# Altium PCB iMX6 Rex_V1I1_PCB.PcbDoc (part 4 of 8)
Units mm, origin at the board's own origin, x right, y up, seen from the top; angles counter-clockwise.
Board outline 70 x 40 mm, 12 copper layers (L1, L2, L3, L4, L5 (PWR), L6 (PWR), L7 (PWR), L8 (PWR), L9, L10, L11, L12), stack 1.566 mm thick; 473 components, 409 nets, 2294 pads, 1880 vias.
Unrouted connection lines stored in the file: 7.
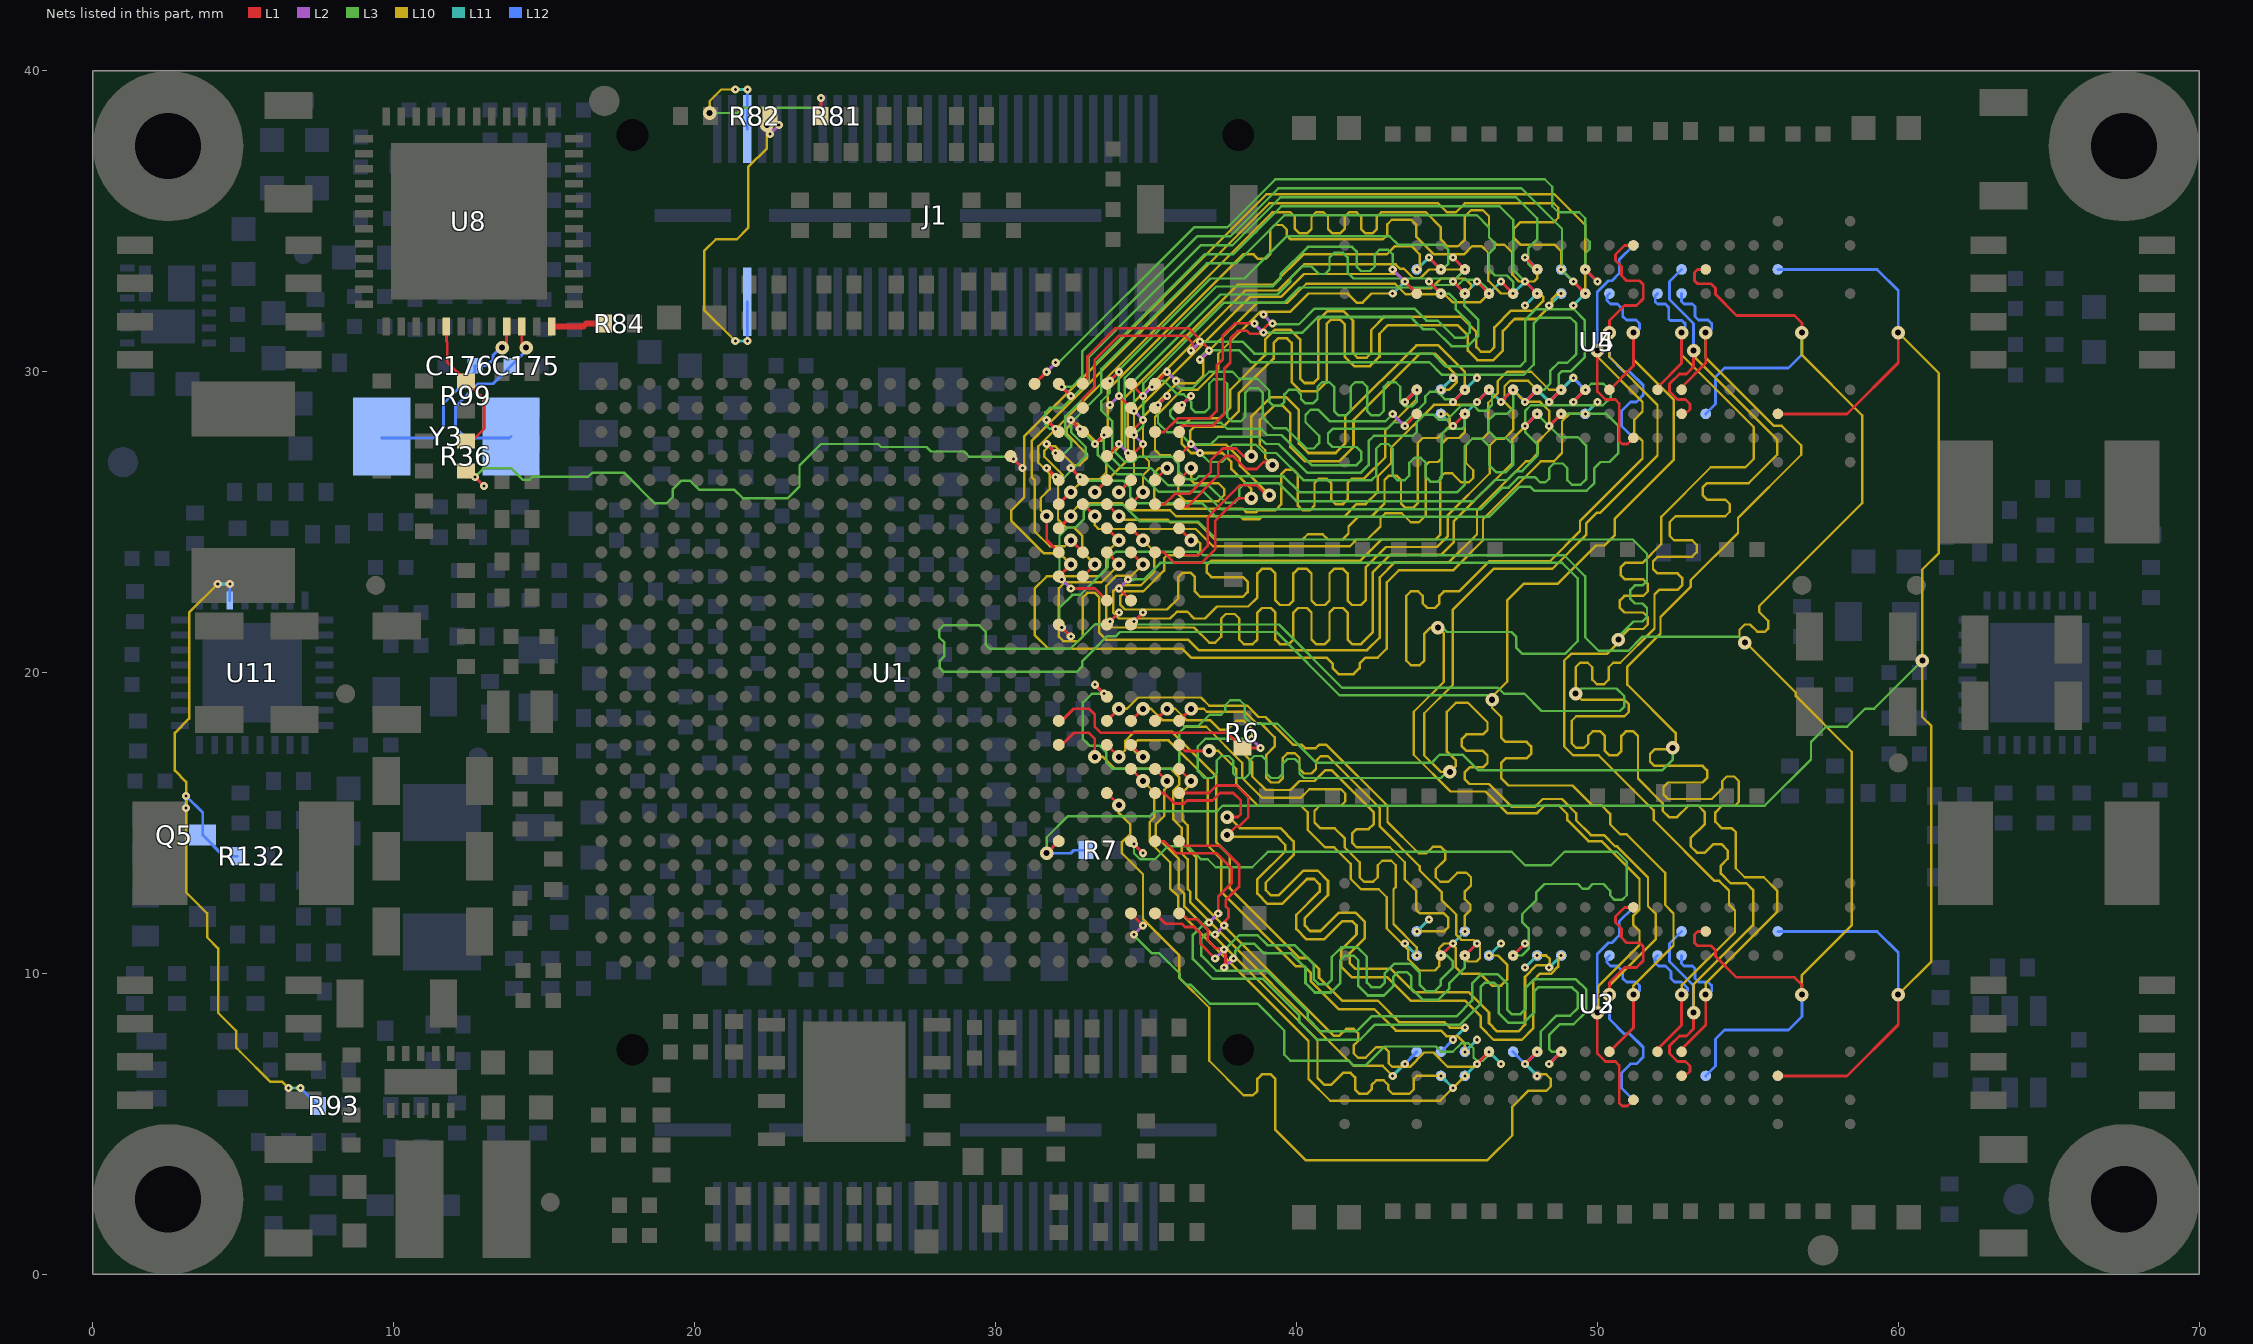
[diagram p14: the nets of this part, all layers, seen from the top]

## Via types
v1: diameter 0.45, hole 0.2, L1 to L12, tented both sides, 761 vias
v2: diameter 0.27, hole 0.1, L1 to L2, 305 vias
v3: diameter 0.27, hole 0.1, L2 to L3, 290 vias
v4: diameter 0.45, hole 0.2, L3 to L10, 196 vias
v5: diameter 0.27, hole 0.1, L11 to L12, 185 vias
v6: diameter 0.27, hole 0.1, L10 to L11, 142 vias
v7: diameter 0.45, hole 0.2, L3 to L10, tented both sides, 1 vias

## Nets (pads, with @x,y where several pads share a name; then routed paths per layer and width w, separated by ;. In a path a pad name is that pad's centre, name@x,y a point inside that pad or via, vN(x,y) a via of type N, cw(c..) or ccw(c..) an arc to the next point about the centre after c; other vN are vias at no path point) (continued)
DRAM_D24: U1.AE9 U3.D7 | length 19.8
  L1 w0.093: U1.AE9@36.1,16.8 v1(36.5,16.4)
  L10 w0.08: v1(36.5,16.4) 36.5,16.3 36.213,16.013 36.213,15.1 36.383,14.93 36.383,14.153 36.675,13.86 36.675,12.495 41.232,7.938 41.43,7.938 41.654,8.162 41.904,8.162 42.054,8.012 42.054,7.762 41.9,7.608 ; 41.9,7.6 41.9,7.35 42.05,7.2 42.3,7.2 42.654,7.554 ; 42.662,7.554 42.912,7.554 43.062,7.404 43.062,7.021 43.183,6.9 43.77,6.9 44.245,7.375 44.555,7.375 45.03,6.9 45.9,6.9 v6(46.4,7.4)
  L11 w0.1: v6(46.4,7.4) v5(46.8,7)
  L12 w0.093: v6(46.4,7.4) v5(46.8,7)
DRAM_D25: U1.Y10 U3.A7 | length 19.9
  L1 w0.093: U1.Y10@32.1,17.6 32.2,17.6 32.6,18 33.1,18 33.3,17.8 v1(33.3,17.2)
  L10 w0.08: v1(33.3,17.2) 33.57,17.2 33.97,16.8 35.83,16.8 36.1,16.53 36.1,16.27 35.909,16.078 35.909,15.122 36.183,14.847 36.183,14 36.383,13.8 36.383,12.813 36.475,12.721 36.475,12.362 41.9,6.937 42.863,6.937 v6(43.2,6.6)
  L11 w0.1: v6(43.2,6.6) v5(43.6,7)
  L12 w0.093: v5(43.6,7) U3.A7@44,7.4
DRAM_D26: U1.AE11 U3.C3 | length 19.8
  L1 w0.093: U1.AE11@36.1,18.4 v1(36.5,18.8)
  L10 w0.08: v1(36.5,18.8) 36.917,18.8 37.017,18.7 38.287,18.7 38.662,18.325 38.805,18.325 39.275,17.855 39.275,17.545 39,17.27 39,16.5 39.15,16.35 39.4,16.35 39.55,16.5 39.55,17.17 39.7,17.32 39.95,17.32 40.1,17.17 40.1,16.8 40.25,16.65 40.5,16.65 40.65,16.8 40.65,17.07 40.8,17.22 41.05,17.22 42.775,15.495 42.775,14.888 44.1,13.563 44.1,13.43 44.825,12.705 44.825,12.445 45.315,11.955 45.315,11.282 45.482,11.115 45.885,11.115 46.1,10.9 46.1,10.52 45.98,10.4 45.7,10.4 45.6,10.5 v6(45.6,10.6)
  L11 w0.1: v6(45.6,10.6) v5(46,11)
  L12 w0.093: v6(45.6,10.6) v5(46,11)
DRAM_D27: U1.AB11 U3.C2 | length 19.8
  L1 w0.093: U1.AB11@33.7,18.4 v1(34.1,18.8)
  L10 w0.08: v1(34.1,18.8) 34.37,18.8 34.745,19.175 36.825,19.175 37.1,18.9 38.37,18.9 38.745,18.525 38.975,18.525 39.9,17.6 40.181,17.6 40.291,17.491 40.641,17.491 40.75,17.6 41,17.6 43.025,15.575 43.025,15.041 44.066,14 44.321,14 44.53,14.209 44.8,14.209 44.95,14.059 44.95,13.789 44.63,13.47 44.63,13.2 44.78,13.05 45.05,13.05 45.35,13.35 45.65,13.35 45.8,13.2 45.8,12.93 45.6,12.73 45.6,12.47 45.785,12.285 45.785,12.115 45.6,11.93 v6(45.6,11.4)
  L11 w0.1: v5(45.2,11) v6(45.6,11.4)
  L12 w0.093: v5(45.2,11) v6(45.6,11.4)
DRAM_D28: U1.AC9 U3.C8 | length 19.8
  L1 w0.093: U1.AC9@34.5,16.8 v1(34.9,16.4)
  L10 w0.08: v1(34.9,16.4) 35.275,16.025 35.275,15.188 35.125,15.038 35.125,14.375 35.8,13.7 35.8,12.83 36.075,12.555 36.075,12.079 40.4,7.754 40.4,6.5 41.125,5.775 44.775,5.775 v6(45.6,6.6)
  L11 w0.1: v6(45.6,6.6) v5(46,7)
  L12 w0.093: v6(45.6,6.6) v5(46,7)
DRAM_D29: U1.AD9 U3.B8 | length 19.8
  L1 w0.093: U1.AD9@35.3,16.8 v1(35.7,16.4)
  L10 w0.08: v1(35.7,16.4) 35.7,16.2 35.604,16.104 35.604,15.235 35.325,14.955 35.325,14.575 36.092,13.809 36.092,12.822 36.275,12.638 36.275,12.225 40.7,7.8 40.7,6.53 40.93,6.3 41.15,6.3 41.55,6.7 41.8,6.7 41.95,6.55 41.95,6.15 42.1,6 42.35,6 42.5,6.15 42.5,6.3 42.65,6.45 42.9,6.45 43.05,6.3 43.05,6.15 43.2,6 43.75,6 43.9,6.15 43.9,6.5 44,6.6 v6(44.8,6.6)
  L11 w0.1: v6(44.8,6.6) v5(45.2,6.2)
  L12 w0.093: v6(44.8,6.6) v5(45.2,6.2)
DRAM_D30: U1.AD11 U3.A2 | length 19.8
  L1 w0.093: U1.AD11@35.3,18.4 v1(35.7,18.8)
  L10 w0.08: v1(35.7,18.8) 35.97,18.8 36.345,18.425 37.132,18.425 37.457,18.1 37.7,18.1 38,18.4 38.243,18.4 38.525,18.118 38.525,17.875 38.225,17.575 38.225,17.332 38.525,17.032 38.525,16.558 38.983,16.1 39.8,16.1 40.1,16.4 40.6,16.4 40.95,16.75 41.18,16.75 42.575,15.355 42.575,14.975 42.4,14.8 42,14.8 41.85,14.65 41.85,14.35 42,14.2 43.1,14.2 43.6,13.7 43.6,13.13 43.975,12.755 43.975,12.125 44.1,12 44.9,12 45.05,11.85 45.05,11.55 44.9,11.4 v6(44,11.4)
  L11 w0.1: v6(44,11.4) v5(44.4,11.8)
  L12 w0.093: v6(44,11.4) v5(44.4,11.8)
DRAM_D31: U1.AC11 U3.A3 | length 19.8
  L1 w0.093: U1.AC11@34.5,18.4 v1(34.9,18.8)
  L10 w0.08: v1(34.9,18.8) 35.17,18.8 35.545,18.425 36.062,18.425 36.287,18.2 37,18.2 38.2,17 38.2,16.5 38.863,15.837 40.137,15.837 40.425,16.125 41.475,16.125 41.625,15.975 41.625,15.725 41.475,15.575 40.775,15.575 40.6,15.4 40.6,15.02 40.795,14.825 41.275,14.825 41.6,14.5 41.6,14.2 42.1,13.7 42.1,13.2 42.25,13.05 42.55,13.05 42.7,13.2 42.7,13.6 42.85,13.75 43.15,13.75 43.3,13.6 43.3,12.875 43.225,12.8 43.225,11.645 44,10.87 v6(44,10.6)
  L11 w0.1: v5(43.6,11) v6(44,10.6)
  L12 w0.093: v5(43.6,11) v6(44,10.6)
DRAM_D32: U1.AA17 U5.E3 | length 31.9
  L1 w0.093: U1.AA17@32.9,23.2 v1(33.3,23.6)
  L10 w0.08: v1(33.3,23.6) 32.875,24.025 32.875,24.555 32.605,24.825 32.345,24.825 32.075,25.095 32.075,26.205 32.235,26.365 32.235,26.565 31.622,27.177 31.622,27.377 31.773,27.527 31.972,27.527 32.6,26.9 32.8,26.9 33.025,27.125 33.025,27.275 32.373,27.928 32.373,28.127 32.523,28.277 32.722,28.277 33.3,27.7 33.5,27.7 33.725,27.925 33.725,29.397 38.228,33.9 38.578,33.9 38.728,33.75 38.978,33.75 39.128,33.9 39.128,34.728 39.278,34.878 39.528,34.878 39.678,34.728 39.678,34.522 39.8,34.4 42.87,34.4 43.02,34.55 43.02,34.9 43.17,35.05 43.815,35.05 43.975,34.89 43.975,34.495 44.57,33.9 45.57,33.9 45.845,34.175 46.155,34.175 46.375,33.955 46.375,33.028 46.803,32.6 v6(47.2,32.6)
  L11 w0.1: v6(47.2,32.6) v5(47.6,33)
  L12 w0.093: v6(47.2,32.6) v5(47.6,33)
DRAM_D33: U1.AA18 U5.G2 | length 31.9
  L1 w0.093: v1(32.5,24.4) U1.AA18@32.9,24
  L10 w0.08: v1(32.5,24.4) 32.3,24.2 31.8,24.2 31.3,24.7 31.3,26.4 31.2,26.5 31.2,27.7 39.1,35.6 44.7,35.6 45,35.3 45.3,35.3 45.6,35.6 48.55,35.6 48.7,35.45 48.7,35.12 48.555,34.975 47.445,34.975 47.225,34.755 47.225,34.445 47.445,34.225 48.575,34.225 48.8,34 v6(48.8,33.4)
  L11 w0.1: v6(48.8,33.4) v5(49.2,33)
  L12 w0.093: v6(48.8,33.4) v5(49.2,33)
DRAM_D34: U1.AC18 U5.F8 | length 31.9
  L1 w0.093: U1.AC18@34.5,24 v1(34.9,23.6)
  L10 w0.08: v1(34.9,23.6) 34.525,23.225 34.021,23.225 33.683,22.887 33.683,21.702 33.885,21.5 36.6,21.5 37.1,21 37.3,21 37.5,21.2 37.5,21.8 37.65,21.95 37.95,21.95 38.1,21.8 38.1,21.1 38.25,20.95 38.55,20.95 38.7,21.1 38.7,22 38.85,22.15 39.15,22.15 39.3,22 39.3,21.1 39.45,20.95 39.75,20.95 39.9,21.1 39.9,22 40.05,22.15 40.35,22.15 40.5,22 40.5,21.1 40.65,20.95 40.95,20.95 41.1,21.1 41.1,22 41.25,22.15 41.55,22.15 41.7,22 41.7,21.1 41.85,20.95 42.15,20.95 42.533,21.333 42.533,23.333 43.125,23.925 44.825,23.925 45.225,24.325 45.225,25.025 47.175,26.975 47.175,27.762 48,28.587 v6(48,28.6)
  L11 w0.1: v5(47.6,28.2) v6(48,28.6)
  L12 w0.093: v5(47.6,28.2) v6(48,28.6)
DRAM_D35: U1.AE19 U5.H7 | length 31.9
  L1 w0.093: U1.AE19@36.1,24.8 v1(36.5,24.4)
  L10 w0.08: v1(36.5,24.4) 36.7,24.4 36.8,24.3 36.8,24 36.7,23.9 35.7,23.9 35.6,23.8 35.6,23.392 34.908,22.7 34.3,22.7 34.15,22.55 34.15,22.25 34.3,22.1 35.7,22.1 36.075,22.475 36.075,23.175 36.225,23.325 36.475,23.325 36.625,23.175 36.625,22.7 36.8,22.525 38.225,22.525 38.375,22.675 38.375,23.025 38.225,23.175 37.175,23.175 37.025,23.325 37.025,23.575 37.175,23.725 42.125,23.725 42.825,24.425 44.625,24.425 44.775,24.575 44.775,26.475 44.925,26.625 45.175,26.625 45.475,26.325 45.725,26.325 45.875,26.475 45.875,26.725 45.625,26.975 45.625,27.555 45.845,27.775 46.18,27.775 46.375,27.97 46.375,28.972 46.685,29.282 46.685,29.685 47,30 47.803,30 48.403,29.4 v6(48.8,29.4)
  L11 w0.1: v6(48.8,29.4) v5(49.2,29.8)
  L12 w0.093: v5(49.2,29.8) U5.H7@49.6,29.4
DRAM_D36: U1.Y17 U5.H3 | length 31.9
  L1 w0.093: U1.Y17@32.1,23.2 v1(32.5,23.6)
  L10 w0.08: v1(32.5,23.6) 32.125,23.975 31.595,23.975 30.525,25.045 30.525,25.4 30.95,25.825 30.95,27.85 39,35.9 48.575,35.9 49.6,34.875 v6(49.6,32.6)
  L11 w0.1: v5(49.2,32.2) v6(49.6,32.6)
  L12 w0.093: v5(49.2,32.2) v6(49.6,32.6)
DRAM_D37: U1.Y18 U5.F2 | length 31.9
  L1 w0.093: v1(31.7,25.2) 31.7,24.4 U1.Y18@32.1,24
  L10 w0.08: v1(31.7,25.2) 31.5,25.4 31.5,25.8 31.8,26.1 31.8,26.6 31.423,26.978 31.423,27.522 39.2,35.3 39.8,35.3 39.95,35.15 39.95,34.75 40.1,34.6 40.35,34.6 40.5,34.75 40.5,35.15 40.65,35.3 40.9,35.3 41.05,35.15 41.05,34.75 41.2,34.6 41.45,34.6 41.6,34.75 41.6,35.15 41.75,35.3 42,35.3 42.15,35.15 42.15,34.75 42.3,34.6 42.525,34.6 42.675,34.75 42.675,35.15 42.825,35.3 44.3,35.3 44.8,34.8 44.8,34.4 45.03,34.17 45.37,34.17 45.6,34.4 45.6,35.17 45.8,35.37 46.2,35.37 46.4,35.17 46.4,34.47 46.645,34.225 46.905,34.225 47.175,33.955 47.175,33.225 47.4,33 47.9,33 48,33.1 v6(48,33.4)
  L11 w0.1: v5(47.6,33.8) v6(48,33.4)
  L12 w0.093: v5(47.6,33.8) v6(48,33.4)
DRAM_D38: U1.AB19 U5.H8 | length 31.9
  L1 w0.093: U1.AB19@33.7,24.8 v1(34.1,24.4)
  L10 w0.08: v1(34.1,24.4) 33.675,23.975 33.675,23.445 33.43,23.2 31.7,23.2 31.3,22.8 31.3,21.25 31.75,20.8 36.2,20.8 36.5,20.5 41,20.5 41.2,20.3 41.2,20.15 41.4,19.95 41.9,19.95 42.1,20.15 42.1,20.3 42.3,20.5 42.7,20.5 43,20.8 43,23 43.4,23.4 45.2,23.4 46.2,24.4 46.2,25.1 48.125,27.025 48.555,27.025 48.825,27.295 48.825,28.355 49.07,28.6 v6(49.6,28.6)
  L11 w0.1: v6(49.6,28.6) v5(50,29)
  L12 w0.093: v6(49.6,28.6) v5(50,29)
DRAM_D39: U1.AC19 U5.F7 | length 31.9
  L1 w0.093: U1.AC19@34.5,24.8 v1(34.9,24.4)
  L10 w0.08: v1(34.9,24.4) 35.275,24.025 35.275,23.35 34.825,22.9 34.1,22.9 33.917,22.717 33.917,21.983 34.1,21.8 35.8,21.8 36.025,22.025 36.375,22.025 36.6,21.8 36.958,21.8 37.358,22.2 38.4,22.2 38.7,22.5 38.7,23.3 38.85,23.45 39.15,23.45 39.3,23.3 39.3,22.4 39.45,22.25 39.75,22.25 39.9,22.4 39.9,23.3 40.05,23.45 40.35,23.45 40.5,23.3 40.5,22.4 40.65,22.25 40.95,22.25 41.1,22.4 41.1,23.3 41.25,23.45 41.55,23.45 41.7,23.3 41.7,22.4 41.85,22.25 42.15,22.25 42.3,22.4 42.3,23.5 42.975,24.175 44.675,24.175 45.025,24.525 45.025,25.225 46.425,26.625 46.425,27.555 46.645,27.775 46.905,27.775 47.2,28.07 47.2,28.715 46.915,29 46.915,29.518 47.097,29.7 47.7,29.7 v6(48,29.4)
  L11 w0.1: v6(48,29.4) v5(48.4,29)
  L12 w0.093: v6(48,29.4) v5(48.4,29)
DRAM_D40: U1.Y19 U5.D7 | length 18.4
  L1 w0.093: U1.Y19@32.1,24.8 v1(32.5,25.2)
  L10 w0.08: v1(32.5,25.2) 32.5,25.3 32.825,25.625 34.205,25.625 34.43,25.4 35.8,25.4 36,25.2 38.125,25.2 38.225,25.1 38.77,25.1 38.845,25.175 41.575,25.175 42,25.6 42.3,25.6 42.7,26 42.7,26.517 43.15,26.967 43.15,27.48 44.57,28.9 45.9,28.9 v6(46.4,29.4)
  L11 w0.1: v6(46.4,29.4) v5(46.8,29)
  L12 w0.093: v6(46.4,29.4) v5(46.8,29)
DRAM_D41: U1.AB20 U5.B8 | length 18.5
  L1 w0.093: U1.AB20@33.7,25.6 v1(34.1,25.2)
  L10 w0.08: v1(34.1,25.2) 34.213,25.088 35.712,25.088 35.8,25 36.713,25 37.288,24.425 40.2,24.425 40.375,24.6 40.87,24.6 41.045,24.425 41.525,24.425 41.73,24.63 41.73,24.861 42.045,25.175 42.475,25.175 42.925,25.625 42.925,26.4 43.075,26.55 43.325,26.55 43.475,26.4 43.475,25.625 43.625,25.475 43.875,25.475 44.025,25.625 44.025,27.625 44.2,27.8 44.7,27.8 45.1,28.2 45.1,28.5 45,28.6 v6(44.8,28.6)
  L11 w0.1: v6(44.8,28.6) v5(45.2,28.2)
  L12 w0.093: v6(44.8,28.6) v5(45.2,28.2)
DRAM_D42: U1.AB21 U5.C2 | length 18.4
  L1 w0.093: v1(33.3,26) U1.AB21@33.7,26.4
  L10 w0.08: v1(33.3,26) 33.313,26 34.4,27.087 34.4,28.8 38.3,32.7 39.383,32.7 40.258,33.575 43.295,33.575 43.445,33.425 43.572,33.425 43.882,33.115 44.118,33.115 44.403,33.4 v6(45.6,33.4)
  L11 w0.1: v5(45.2,33) v6(45.6,33.4)
  L12 w0.093: v5(45.2,33) v6(45.6,33.4)
DRAM_D43: U1.AD21 U5.A7 | length 18.4
  L1 w0.093: U1.AD21@35.3,26.4 v1(35.7,26.8)
  L10 w0.08: v1(35.7,26.8) 35.434,26.8 35.275,26.641 35.275,25.825 35.5,25.6 36,25.6 36.15,25.45 38.22,25.45 38.345,25.325 38.655,25.325 38.73,25.4 39.3,25.4 39.5,25.6 39.5,26.6 39.65,26.75 39.9,26.75 40.05,26.6 40.05,25.55 40.2,25.4 40.45,25.4 40.6,25.55 40.6,26.3 40.75,26.45 41,26.45 41.15,26.3 41.15,25.75 41.3,25.6 41.55,25.6 41.7,25.75 41.7,26.3 41.85,26.45 42.25,26.45 42.95,27.15 42.95,28.05 44,29.1 v6(44,29.4)
  L11 w0.1: v5(43.6,29) v6(44,29.4)
  L12 w0.093: v5(43.6,29) v6(44,29.4)
DRAM_D44: U1.Y20 U5.A2 | length 18.4
  L1 w0.093: U1.Y20@32.1,25.6 v1(32.5,26)
  L10 w0.08: v1(32.5,26) 32.925,26.425 33.455,26.425 33.675,26.645 33.675,27.075 34.2,27.6 34.2,29.046 38.054,32.9 39.23,32.9 40.23,33.9 43,33.9 43.275,34.175 43.825,34.175 44.1,33.9 44.1,33.5 v6(44,33.4)
  L11 w0.1: v6(44,33.4) v5(44.4,33.8)
  L12 w0.093: v6(44,33.4) v5(44.4,33.8)
DRAM_D45: U1.AA20 U5.C8 | length 18.4
  L1 w0.093: U1.AA20@32.9,25.6 v1(33.3,25.2)
  L10 w0.08: v1(33.3,25.2) 33.3,24.9 33.425,24.775 36.655,24.775 37.23,24.2 41.775,24.2 42,24.425 42.355,24.425 42.793,24.863 42.793,25.136 42.957,25.3 43.5,25.3 43.8,25 44.07,25 44.3,25.23 44.3,26.9 44.4,27 44.7,27 44.825,27.125 44.825,27.6 45.025,27.8 45.4,27.8 45.6,28 v6(45.6,28.6)
  L11 w0.1: v6(45.6,28.6) v5(46,29)
  L12 w0.093: v6(45.6,28.6) v5(46,29)
DRAM_D46: U1.AE21 U5.A3 | length 18.5
  L1 w0.093: U1.AE21@36.1,26.4 v1(36.5,26.8)
  L10 w0.08: v1(36.5,26.8) 36.5,26.4 36.6,26.3 37.4,26.3 37.6,26.1 37.6,25.9 37.4,25.7 36.3,25.7 36.075,25.925 36.075,26.955 35.805,27.225 35.475,27.225 35.3,27.4 35.3,28.5 36.2,29.4 36.713,29.4 37.4,30.087 37.4,30.6 38.8,32 39.8,32 40.4,32.6 41.7,32.6 42,32.3 42.2,32.3 42.5,32.6 v6(43.2,32.6)
  L11 w0.1: v6(43.2,32.6) v5(43.6,33)
  L12 w0.093: v5(43.6,33) U5.A3@44,32.6
DRAM_D47: U1.AC21 U5.C3 | length 18.4
  L1 w0.093: v1(34.1,26) U1.AC21@34.5,26.4
  L10 w0.08: v1(34.1,26) 34.6,26.5 34.6,28.63 38.47,32.5 39.5,32.5 40.25,33.25 43.337,33.25 43.812,32.775 44.475,32.775 44.8,33.1 45.6,33.1 45.8,32.9 45.8,32.8 v6(45.6,32.6)
  L11 w0.1: v6(45.6,32.6) v5(46,33)
  L12 w0.093: v6(45.6,32.6) v5(46,33)
DRAM_D48: U1.AC22 U4.D7 | length 17.1
  L1 w0.093: U1.AC22@34.5,27.2 v2(34.9,27.6) ; v2(46,33) v3(46.4,32.6)
  L2 w0.1: v3(34.6,27.9) v2(34.9,27.6) ; v2(46,33) v3(46.4,32.6)
  L3 w0.08: v3(34.6,27.9) 34.915,28.215 34.915,29.618 37.597,32.3 39.6,32.3 40.1,32.8 44.538,32.8 44.623,32.885 45.368,32.885 45.541,33.059 46.041,33.059 46.4,32.7 v3(46.4,32.6)
DRAM_D49: U1.AE22 U4.C2 | length 17.1
  L1 w0.093: U1.AE22@36.1,27.2 v2(36.5,27.6) ; v2(45.2,28.2) v3(45.6,28.6)
  L2 w0.1: v2(36.5,27.6) v3(36.8,27.3) ; v2(45.2,28.2) v3(45.6,28.6)
  L3 w0.08: v3(36.8,27.3) 37.1,27 37.525,27 37.725,27.2 37.725,27.425 37.875,27.575 38.655,27.575 38.93,27.3 39.33,27.3 40.23,26.4 42.5,26.4 42.65,26.55 42.65,27.45 42.8,27.6 43.05,27.6 43.2,27.45 43.2,26.55 43.35,26.4 43.6,26.4 43.75,26.55 43.75,26.97 43.925,27.145 44.125,27.145 44.3,26.97 44.3,26.5 44.45,26.35 44.7,26.35 44.825,26.475 44.825,27.925 45,28.1 45.5,28.1 45.6,28.2 v3(45.6,28.6)
DRAM_D50: U1.AE24 U4.C3 | length 17.1
  L1 w0.093: U1.AE24@36.1,28.8 v2(36.5,29.2) ; v2(45.2,29) v3(45.6,29.4)
  L2 w0.1: v3(36.2,28.9) v2(36.5,29.2) ; v2(45.2,29) v3(45.6,29.4)
  L3 w0.08: v3(36.2,28.9) 36,28.9 35.8,28.7 35.8,28.55 36.05,28.3 37.5,28.3 37.7,28.1 38.825,28.1 39.025,27.9 39.5,27.9 40.5,26.9 42,26.9 42.15,27.05 42.15,27.35 42,27.5 41.2,27.5 41.05,27.65 41.05,27.95 41.2,28.1 43.017,28.1 43.232,28.315 43.615,28.315 44.285,28.985 44.285,29.185 44.435,29.335 44.685,29.335 44.935,29.085 45.285,29.085 v3(45.6,29.4)
DRAM_D51: U1.AC24 U4.B8 | length 17.2
  L1 w0.093: v2(34.1,29.2) U1.AC24@34.5,28.8 ; v2(44.4,33.8) v3(44.8,33.4)
  L2 w0.1: v3(33.8,28.9) v2(34.1,29.2) ; v2(44.4,33.8) v3(44.8,33.4)
  L3 w0.08: v3(33.8,28.9) v2(34.1,29.2) 34.1,30.055 37.145,33.1 38.27,33.1 39.67,34.5 43.1,34.5 43.375,34.225 44.875,34.225 45.05,34.05 45.05,33.6 44.85,33.4 v3(44.8,33.4)
DRAM_D52: U1.AB22 U4.A7 | length 17.2
  L1 w0.093: U1.AB22@33.7,27.2 v2(34.1,27.6) ; v2(43.6,33) U4.A7@44,32.6
  L2 w0.1: v2(34.1,27.6) v3(34.4,27.3) ; v3(43.2,33.4) v2(43.6,33)
  L3 w0.08: v3(34.4,27.3) 34.3,27.4 34.3,29.8 37.333,32.833 39.208,32.833 39.475,33.1 39.475,33.245 40.38,34.15 41.85,34.15 42,34 42,33.5 42.15,33.35 42.45,33.35 42.6,33.5 42.6,33.9 42.75,34.05 43.05,34.05 43.2,33.9 v3(43.2,33.4)
DRAM_D53: U1.AC23 U4.C8 | length 17.2
  L1 w0.093: U1.AC23@34.5,28 v2(34.9,28.4) ; v2(45.2,33.8) v3(45.6,33.4)
  L2 w0.1: v3(34.6,28.7) v2(34.9,28.4) ; v2(45.2,33.8) v3(45.6,33.4)
  L3 w0.08: v3(34.6,28.7) 34.6,29.695 37.471,32.567 39.367,32.567 39.8,33 39.8,33.117 40.183,33.5 40.5,33.5 40.75,33.25 40.95,33.25 41.1,33.4 41.1,33.8 41.25,33.95 41.55,33.95 41.7,33.8 41.7,33.3 41.9,33.1 45.3,33.1 v3(45.6,33.4)
DRAM_D54: U1.AD25 U4.A3 | length 17.1
  L1 w0.093: U1.AD25@35.3,29.6 v2(35.7,30) ; v2(43.6,29) v3(44,29.4)
  L2 w0.1: v2(35.7,30) v3(36,29.7) ; v2(43.6,29) v3(44,29.4)
  L3 w0.08: v3(36,29.7) 36,29.6 36.15,29.45 36.55,29.45 37.1,30 37.87,30 38.1,29.77 38.7,29.77 39.1,29.37 39.1,29 39.225,28.875 39.475,28.875 39.6,29 39.6,29.25 39.75,29.4 40,29.4 40.15,29.25 40.15,29.1 40.3,28.95 40.55,28.95 40.7,29.1 40.7,29.5 40.85,29.65 41.1,29.65 41.25,29.5 41.25,28.7 41.4,28.55 41.65,28.55 41.8,28.7 41.8,29.5 41.95,29.65 42.2,29.65 42.35,29.5 42.35,28.7 42.5,28.55 42.75,28.55 42.9,28.7 42.9,29.5 43.05,29.65 43.3,29.65 43.45,29.5 43.45,29 43.6,28.85 43.85,28.85 44,29 v3(44,29.4)
DRAM_D55: U1.AC25 U4.A2 | length 17.1
  L1 w0.093: U1.AC25@34.5,29.6 v2(34.9,29.2) ; v2(43.6,28.2) U4.A2@44,28.6
  L2 w0.1: v2(34.9,29.2) v3(35.2,29.5) ; v3(43.2,28.6) v2(43.6,28.2)
  L3 w0.08: v3(35.2,29.5) 35.4,29.7 35.597,29.7 36.047,29.25 36.253,29.25 36.5,29.003 36.5,28.8 36.65,28.65 36.95,28.65 37.1,28.8 37.1,29.6 37.25,29.75 37.55,29.75 37.7,29.6 37.7,28.5 37.85,28.35 38.15,28.35 38.3,28.5 38.3,29.3 38.45,29.45 38.737,29.45 38.887,29.3 38.887,28.483 39.245,28.125 39.658,28.125 40.331,27.451 40.575,27.451 40.751,27.628 40.751,27.871 40.3,28.323 40.3,28.566 40.477,28.743 40.72,28.743 41.113,28.35 42.95,28.35 v3(43.2,28.6)
DRAM_D56: U1.AB25 U4.E3 | length 25
  L1 w0.093: U1.AB25@33.7,29.6 v2(34.1,30) ; v2(46.8,29) v3(47.2,29.4)
  L2 w0.1: v3(33.8,29.7) v2(34.1,30) ; v2(46.8,29) v3(47.2,29.4)
  L3 w0.08: v3(33.8,29.7) 33.8,29.303 33.515,29.018 33.515,28.715 33.885,28.345 33.885,27.412 34.282,27.015 34.6,27.015 34.76,27.175 35.855,27.175 36.075,26.955 36.075,26.695 36.345,26.425 36.655,26.425 36.755,26.525 39.575,26.525 40.1,26 45.35,26 45.6,26.25 45.6,27.53 45.845,27.775 46.155,27.775 46.4,27.53 46.4,26.9 46.645,26.655 46.955,26.655 47.2,26.9 47.2,27.575 46.975,27.8 46.62,27.8 46.375,28.045 46.375,28.375 46.6,28.6 47,28.6 47.2,28.8 v3(47.2,29.4)
DRAM_D57: U1.AA21 U4.G2 | length 25
  L1 w0.093: v2(32.5,26.8) U1.AA21@32.9,26.4 ; v2(48.4,28.2) v3(48.8,28.6)
  L2 w0.1: v2(32.5,26.8) v3(32.8,26.5) ; v2(48.4,28.2) v3(48.8,28.6)
  L3 w0.08: v3(32.8,26.5) 32.925,26.375 34.255,26.375 34.475,26.155 34.475,25.85 34.7,25.625 36.875,25.625 37.325,25.175 46.4,25.175 47.4,26.175 47.775,26.175 47.9,26.05 49.65,26.05 49.9,26.3 49.9,26.8 50.1,27 50.4,27 50.7,27.3 50.7,28.2 50.3,28.6 v3(48.8,28.6)
DRAM_D58: U1.Y25 U4.H7 | length 25
  L1 w0.093: U1.Y25@32.1,29.6 v2(32.5,29.2) ; v2(49.2,33) v3(49.6,32.6)
  L2 w0.1: v3(32.2,29.5) v2(32.5,29.2) ; v2(49.2,33) v3(49.6,32.6)
  L3 w0.08: v3(32.2,29.5) 32.53,29.5 32.875,29.845 32.875,30.675 36.7,34.5 37.8,34.5 39.4,36.1 47.48,36.1 48.825,34.755 48.825,33.375 v3(49.6,32.6)
DRAM_D59: U1.Y22 U4.F7 | length 25
  L1 w0.093: v2(31.7,27.6) U1.Y22@32.1,27.2 ; v2(47.6,33) v3(48,32.6)
  L2 w0.1: v2(31.7,27.6) v3(32,27.3) ; v2(47.6,33) v3(48,32.6)
  L3 w0.08: v3(32,27.3) 32.3,27.3 32.514,27.514 32.514,27.7 32.315,27.899 32.315,28.515 33.3,29.5 33.3,30.255 36.945,33.9 37.9,33.9 39.5,35.5 46.75,35.5 47.2,35.05 47.2,33.4 v3(48,32.6)
DRAM_D60: U1.AB23 U4.H3 | length 25
  L1 w0.093: v2(33.3,27.6) U1.AB23@33.7,28 ; v2(49.2,29) v3(49.6,29.4)
  L2 w0.1: v2(33.3,27.6) v3(33.6,27.9) ; v2(49.2,29) v3(49.6,29.4)
  L3 w0.08: v3(33.6,27.9) 33.6,27.4 34.198,26.802 35.164,26.802 35.741,26.225 37.075,26.225 37.65,25.65 37.95,25.65 38.1,25.8 38.1,26.1 38.3,26.3 39.4,26.3 40,25.7 45.89,25.7 46.594,26.404 47,26.404 47.296,26.7 47.5,26.7 48,27.2 48,27.6 47.6,28 47.6,28.7 47.785,28.885 50.185,28.885 50.45,29.15 50.45,29.35 50.2,29.6 49.8,29.6 v3(49.6,29.4)
DRAM_D61: U1.AA23 U4.F2 | length 25
  L1 w0.093: v2(32.5,28.4) U1.AA23@32.9,28 ; v2(47.6,28.2) v3(48,28.6)
  L2 w0.1: v2(32.5,28.4) v3(32.8,28.1) ; v2(47.6,28.2) v3(48,28.6)
  L3 w0.08: v3(32.8,28.1) 33.4,27.5 33.4,27.23 34.042,26.588 34.842,26.588 35.418,26.012 36.913,26.012 37.5,25.425 46.125,25.425 46.852,26.152 47.052,26.152 47.4,26.5 47.926,26.5 48.1,26.326 48.276,26.326 48.4,26.45 48.4,26.8 48.55,26.95 48.85,26.95 49,26.8 49,26.4 49.15,26.25 49.45,26.25 49.625,26.425 49.625,27.555 49.355,27.825 48.775,27.825 v3(48,28.6)
DRAM_D62: U1.Y23 U4.F8 | length 25
  L1 w0.093: v2(31.7,28.4) U1.Y23@32.1,28 ; v2(47.6,33.8) v3(48,33.4)
  L2 w0.1: v2(31.7,28.4) v3(32,28.1) ; v2(47.6,33.8) v3(48,33.4)
  L3 w0.08: v3(32,28.1) 31.8,28.1 31.65,28.25 31.65,28.65 31.8,28.8 32.2,28.8 33.1,29.7 33.1,30.489 36.811,34.2 37.866,34.2 39.466,35.8 47.3,35.8 48,35.1 48,34.4 47.7,34.1 47.7,33.6 47.9,33.4 v3(48,33.4)
DRAM_D63: U1.W25 U4.H8 | length 25
  L1 w0.093: U1.W25@31.3,29.6 v2(31.7,30) ; v3(49.6,33.4) v2(50,33)
  L2 w0.1: v2(31.7,30) v3(32,30.3) ; v3(49.6,33.4) v2(50,33)
  L3 w0.08: v3(32,30.3) 32.095,30.3 36.595,34.8 37.7,34.8 39.3,36.4 48.25,36.4 48.5,36.15 48.5,35.5 48.7,35.3 49.4,35.3 49.6,35.1 49.6,34.47 49.75,34.32 49.75,34.08 49.6,33.93 v3(49.6,33.4)
DRAM_DQM0: U1.AC3 U2.D3 | length 17.3
  L1 w0.093: U1.AC3@34.5,12 v2(34.9,11.6) ; v2(46,7) v3(46.4,7.4)
  L2 w0.1: v3(34.6,11.3) v2(34.9,11.6) ; v2(46,7) v3(46.4,7.4)
  L3 w0.08: v3(34.6,11.3) 34.6,11.269 35.2,10.669 35.448,10.669 36.125,9.992 36.125,9.845 36.345,9.625 36.492,9.625 37.117,9 38.7,9 39.6,8.1 39.6,7.3 39.8,7.1 41.75,7.1 41.9,6.95 42.3,6.95 42.925,7.575 44.638,7.575 44.813,7.4 45.197,7.4 45.482,7.685 45.718,7.685 45.885,7.518 45.885,7.215 46,7.1 46.2,7.1 46.4,7.3 v3(46.4,7.4)
DRAM_DQM1: U1.AC6 U2.E7 | length 27.6
  L1 w0.093: U1.AC6@34.5,14.4 v2(34.9,14) ; v3(47.2,10.6) v2(47.6,11)
  L2 w0.1: v3(34.6,14.3) v2(34.9,14) ; v3(47.2,10.6) v2(47.6,11)
  L3 w0.08: v3(34.6,14.3) 34.6,14 34.8,13.8 35.3,13.8 35.725,14.225 36.4,14.225 36.825,13.8 37.051,13.8 37.32,13.531 38.531,13.531 39.05,14.05 47.15,14.05 47.6,13.6 48.46,13.6 48.91,14.05 50.65,14.05 50.975,13.725 50.975,12.6 50.825,12.45 50.575,12.45 50.425,12.6 50.425,12.75 50.2,12.975 49.845,12.975 49.685,12.815 49.515,12.815 49.355,12.975 48.245,12.975 47.975,12.705 47.975,12.445 47.5,11.97 47.5,11.715 47.715,11.5 47.715,10.815 47.5,10.6 v3(47.2,10.6)
DRAM_DQM2: U1.AB8 U3.E7 | length 28.5
  L1 w0.093: U1.AB8@33.7,16 v1(34.1,15.6)
  L10 w0.08: v1(34.1,15.6) 34.1,15.33 34.475,14.955 34.475,14.645 34.2,14.37 34.2,14 34.9,13.3 34.9,11.817 36.1,10.617 36.1,9.866 37.1,8.866 37.1,7.1 38.25,5.95 38.55,5.95 38.7,6.1 38.7,6.5 38.85,6.65 39.15,6.65 39.3,6.5 39.3,4.8 40.3,3.8 46.35,3.8 47.175,4.625 47.175,5.575 47.7,6.1 48.3,6.1 48.45,6.25 48.45,6.5 48.3,6.65 48.05,6.65 v6(48,6.6)
  L11 w0.1: v5(47.6,7) v6(48,6.6)
  L12 w0.093: U3.E7@47.2,7.4 v5(47.6,7)
DRAM_DQM3: U1.AE10 U3.D3 | length 19.8
  L1 w0.093: U1.AE10@36.1,17.6 36.3,17.4 v1(37.1,17.4)
  L10 w0.08: v1(37.1,17.4) 37.4,17.4 38,16.8 38,16.3 38.725,15.575 40.155,15.575 40.375,15.355 40.375,14.775 40.95,14.2 41.25,14.2 41.8,13.65 41.8,13.15 42.15,12.8 42.737,12.8 43,12.537 43,11.5 43.715,10.785 43.715,10.482 44.097,10.1 44.6,10.1 44.748,10.248 44.748,10.848 44.9,11 45.148,11 45.3,10.848 45.3,10.2 45.5,10 46.1,10 46.5,9.6 46.8,9.6 47,9.8 47,10.3 46.7,10.6 v6(46.4,10.6)
  L11 w0.1: v6(46.4,10.6) v5(46.8,11)
  L12 w0.093: v6(46.4,10.6) v5(46.8,11)
DRAM_DQM4: U1.AB18 U5.E7 | length 31.9
  L1 w0.093: U1.AB18@33.7,24 v1(34.1,23.6)
  L10 w0.08: v1(34.1,23.6) 34.1,23.587 33.513,23 32.3,23 32.1,22.8 32.1,21.2 32.25,21.05 32.747,21.05 32.9,21.203 32.9,22.5 33.05,22.65 33.3,22.65 33.45,22.5 33.45,21.317 33.667,21.1 36.4,21.1 36.75,20.75 42.35,20.75 42.767,21.167 42.767,23.167 43.275,23.675 45.075,23.675 46,24.6 46,25.4 47.625,27.025 47.755,27.025 48.025,27.295 48.025,27.683 48.4,28.058 48.4,28.7 48.1,29 v5(47.6,29) v6(47.2,29.4)
  L11 w0.1: v6(47.2,29.4) v5(47.6,29)
  L12 w0.093: v6(47.2,29.4) v5(47.6,29)
DRAM_DQM5: U1.AC20 U5.D3 | length 18.4
  L1 w0.093: U1.AC20@34.5,25.6 v1(34.9,26)
  L10 w0.08: v1(34.9,26) 34.9,26.563 35.1,26.763 35.1,27.025 34.9,27.225 34.9,28.5 36.025,29.625 36.655,29.625 36.9,29.87 36.9,30.5 38.7,32.3 39.7,32.3 40.325,32.925 43.278,32.925 43.628,32.575 44.925,32.575 45.185,32.315 46.115,32.315 v6(46.4,32.6)
  L11 w0.1: v6(46.4,32.6) v5(46.8,33)
  L12 w0.093: v6(46.4,32.6) v5(46.8,33)
DRAM_DQM6: U1.AD24 U4.D3 | length 17.1
  L1 w0.093: U1.AD24@35.3,28.8 v2(35.7,29.2) ; v2(46,29) v3(46.4,29.4)
  L2 w0.1: v3(35.4,28.9) v2(35.7,29.2) ; v2(46,29) v3(46.4,29.4)
  L3 w0.08: v3(35.4,28.9) 35.4,28.3 35.71,27.99 36.095,27.99 36.5,27.585 37.147,27.585 37.4,27.837 38.747,27.837 38.984,27.6 39.4,27.6 40.35,26.65 42.15,26.65 42.4,26.9 42.4,27.7 42.573,27.873 43.873,27.873 44,28 44,28.33 44.245,28.575 44.555,28.575 44.73,28.4 44.997,28.4 45.482,28.885 45.885,28.885 46.07,28.7 46.3,28.7 46.5,28.9 46.5,29.3 v3(46.4,29.4)
DRAM_DQM7: U1.Y21 U4.E7 | length 25
  L1 w0.093: v2(31.7,26.8) U1.Y21@32.1,26.4 ; v2(46.8,33) v3(47.2,32.6)
  L2 w0.1: v2(31.7,26.8) v3(32,26.5) ; v2(46.8,33) v3(47.2,32.6)
  L3 w0.08: v3(32,26.5) 32.3,26.5 33,27.2 33,27.497 32.515,27.982 32.515,28.315 33.515,29.315 33.515,30.095 37.02,33.6 38,33.6 39.6,35.2 46,35.2 46.4,34.8 46.4,34.47 46.585,34.285 46.585,34.115 46.4,33.93 46.4,33.4 46.6,33.2 47,33.2 47.2,33 v3(47.2,32.6)
DRAM_DQS0_N: U1.AD3 U2.B7 | length 17.4
  L1 w0.09: U1.AD3@35.3,12 35.645,11.655 36.191,11.655 36.296,11.55 36.6,11.55 36.804,11.346 36.804,10.996 v2(37.3,10.5) ; v3(44.8,10.6) v2(45.2,11)
  L2 w0.1: v2(37.3,10.5) v3(37.6,10.8) ; v3(44.8,10.6) v2(45.2,11)
  L3 w0.085: v3(37.6,10.8) 37.624,10.8 38.097,11.273 38.708,11.273 39.033,10.948 39.94,10.948 40.58,10.308 40.58,9.8 40.73,9.65 41.03,9.65 41.18,9.8 41.18,10.542 ; 41.18,10.558 41.494,10.872 42.026,10.872 42.34,10.558 42.34,9.7 42.49,9.55 42.79,9.55 42.94,9.7 42.94,10.016 43.254,10.33 43.786,10.33 44.1,10.016 44.1,9.616 44.3,9.416 44.6,9.416 44.8,9.616 44.8,9.796 45.2,10.196 45.2,10.4 45,10.6 v3(44.8,10.6)
DRAM_DQS0_P: U1.AE3 U2.C7 | length 17.4
  L1 w0.09: U1.AE3@36.1,12 36.2,12 36.4,11.8 36.704,11.8 37.054,11.45 37.054,11.1 37.314,10.84 37.441,10.84 37.64,10.641 37.64,10.24 v2(37.6,10.2) ; v3(45.6,10.6) v2(46,11)
  L2 w0.1: v2(37.6,10.2) v3(37.9,10.5) ; v3(45.6,10.6) v2(46,11)
  L3 w0.085: v3(37.9,10.5) 37.973,10.573 37.973,10.753 38.213,10.993 38.592,10.993 38.917,10.668 39.825,10.668 40.3,10.192 40.3,9.684 40.614,9.37 41.146,9.37 41.46,9.684 41.46,10.442 41.61,10.592 41.91,10.592 42.06,10.442 42.06,9.584 42.374,9.27 42.906,9.27 43.22,9.584 43.22,9.9 43.37,10.05 43.67,10.05 43.82,9.9 43.82,9.5 44.184,9.136 44.716,9.136 45.08,9.5 45.08,9.68 45.6,10.2 v3(45.6,10.6)
DRAM_DQS1_N: U1.AE6 U2.G3 | length 27.6
  L1 w0.09: U1.AE6@36.1,14.4 36.25,14.25 37.45,14.25 38.1,13.6 38.1,12.9 37.65,12.45 37.65,12.231 37.74,12.141 37.74,11.859 37.6,11.719 v2(37.6,11.6) ; v2(48.4,7) v3(48.8,7.4)
  L2 w0.1: v3(37.3,11.3) v2(37.6,11.6) ; v2(48.4,7) v3(48.8,7.4)
  L3 w0.085: v3(37.3,11.3) 36.973,11.3 36.84,11.168 36.84,10.594 37.334,10.1 39,10.1 40.38,8.72 40.38,8.5 40.8,8.08 42,8.08 42.5,8.58 45.32,8.58 45.84,9.1 45.84,9.666 46.154,9.98 46.686,9.98 47,9.666 47,8.8 47.15,8.65 47.45,8.65 47.62,8.82 47.62,9.52 47.918,9.818 49.278,9.818 49.632,9.463 49.632,8.737 49.216,8.32 48.766,8.32 48.4,7.954 48.4,7.5 48.5,7.4 v3(48.8,7.4)
DRAM_DQS1_P: U1.AD6 U2.F3 | length 27.6
  L1 w0.09: U1.AD6@35.3,14.4 35.6,14.4 36,14 37.346,14 37.85,13.496 37.85,13.004 37.4,12.554 v2(37.4,12) ; v2(47.6,7) v3(48,7.4)
  L2 w0.1: v3(37.1,11.7) v2(37.4,12) ; v2(47.6,7) v3(48,7.4)
  L3 w0.085: v3(37.1,11.7) 36.977,11.7 36.56,11.283 36.56,10.478 37.218,9.82 38.884,9.82 40.1,8.604 40.1,8.384 40.684,7.8 42.116,7.8 42.616,8.3 45.436,8.3 46.12,8.984 46.12,9.55 46.27,9.7 46.57,9.7 46.72,9.55 46.72,8.704 ; 46.72,8.684 47.034,8.37 47.566,8.37 47.9,8.704 47.9,9.404 48.034,9.538 49.162,9.538 49.352,9.348 49.352,8.852 49.1,8.6 48.65,8.6 48.12,8.07 48.12,7.52 v3(48,7.4)
DRAM_DQS2_N: U1.AE8 U3.G3 | length 28.6
  L1 w0.09: U1.AE8@36.1,16 37.1,16 37.35,16.25 38.004,16.25 38.4,15.854 38.4,15.196 38.104,14.9 38.008,14.9 37.708,14.6 v1(37.7,14.6)
  L10 w0.085: v1(37.7,14.6) 37.748,14.552 39.352,14.552 39.628,14.276 39.628,14.064 38.7,13.135 38.7,12.656 39.041,12.315 39.52,12.315 40.348,13.143 40.592,13.143 40.768,12.967 40.768,12.723 40,11.955 40,11.476 40.341,11.135 40.916,11.135 41.516,11.735 41.861,11.735 41.996,11.6 41.996,11.3 41.496,10.8 41.496,10.225 41.837,9.884 43.012,9.884 43.796,9.1 45.604,9.1 46.12,8.584 46.12,8.234 46.554,7.8 47.492,7.8 47.876,8.184 47.876,9.776 48.1,10 48.471,10 48.7,10.229 48.7,10.5 v6(48.8,10.6)
  L11 w0.1: v5(48.4,10.2) v6(48.8,10.6)
  L12 w0.09: v5(48.4,10.2) v6(48.8,10.6)
DRAM_DQS2_P: U1.AD8 U3.F3 | length 28.6
  L1 w0.09: U1.AD8@35.3,16 35.605,16 35.955,15.65 36.27,15.65 36.37,15.75 37.204,15.75 37.454,16 37.9,16 38.15,15.75 38.15,15.3 38.05,15.2 37.75,15.2 v1(37.7,15.2)
  L10 w0.085: v1(37.7,15.2) 37.754,15.2 38.122,14.833 39.468,14.833 39.908,14.392 39.908,13.948 38.98,13.019 38.98,12.772 39.157,12.595 39.404,12.595 40.233,13.423 40.708,13.423 41.048,13.083 41.048,12.607 40.28,11.839 40.28,11.592 40.457,11.415 40.8,11.415 41.4,12.015 41.977,12.015 42.276,11.716 42.276,11.184 41.776,10.684 41.776,10.341 41.953,10.164 43.128,10.164 43.912,9.38 45.72,9.38 46.4,8.7 46.4,8.35 46.67,8.08 47.376,8.08 47.596,8.3 47.596,9.892 47.984,10.28 48.355,10.28 48.42,10.345 48.42,10.48 48.3,10.6 v6(48,10.6)
  L11 w0.1: v5(47.6,10.2) v6(48,10.6)
  L12 w0.09: v5(47.6,10.2) v6(48,10.6)
DRAM_DQS3_N: U1.AB10 U3.B7 | length 19.9
  L1 w0.09: U1.AB10@33.7,17.6 v1(34.1,17.2)
  L10 w0.085: v1(34.1,17.2) 34.1,17.22 34.31,17.43 34.31,17.736 34.604,18.03 35.87,18.03 37.332,16.568 37.332,14.368 37.78,13.92 37.78,12.836 40.1,10.516 40.384,10.516 40.75,10.15 40.75,9.866 41.518,9.098 42.702,9.098 43.42,8.38 44.92,8.38 45.1,8.2 v6(45.6,8.2)
  L11 w0.1: v5(45.2,7.8) v6(45.6,8.2)
  L12 w0.09: U3.B7@44.8,7.4 v5(45.2,7.8)
DRAM_DQS3_P: U1.AC10 U3.C7 | length 19.9
  L1 w0.09: U1.AC10@34.5,17.6 v1(34.9,17.2)
  L10 w0.085: v1(34.9,17.2) 34.814,17.2 34.59,17.424 34.59,17.62 34.72,17.75 35.754,17.75 37.052,16.452 37.052,14.252 37.5,13.804 37.5,12.72 39.984,10.236 40.268,10.236 40.47,10.034 40.47,9.75 41.402,8.818 42.586,8.818 43.304,8.1 44.804,8.1 44.984,7.92 45.35,7.92 45.6,7.67 v6(45.6,7.4)
  L11 w0.1: v6(45.6,7.4) v5(46,7.8)
  L12 w0.09: v6(45.6,7.4) v5(46,7.8)
DRAM_DQS4_N: U1.AE18 U5.G3 | length 32
  L1 w0.09: U1.AE18@36.1,24 36.2,23.9 36.746,23.9 37.05,24.204 37.05,25.15 38.13,26.23 38.678,26.23 39.008,25.9 v1(39.1,25.9)
  L10 w0.085: v1(39.1,25.9) 38.117,26.883 38.117,27.115 37.652,27.58 36.616,27.58 36.466,27.73 36.466,28.03 36.616,28.18 37.576,28.18 38.08,28.684 38.08,29.28 39.24,30.44 39.24,30.96 39.39,31.11 39.69,31.11 39.84,30.96 39.84,29.66 40.154,29.346 40.686,29.346 41,29.66 41,31.584 41.15,31.734 41.45,31.734 41.6,31.584 41.6,30.5 41.914,30.186 42.446,30.186 42.76,30.5 42.76,31.264 43.048,31.552 45.348,31.552 45.7,31.2 45.7,30.7 46.014,30.386 46.546,30.386 46.86,30.7 46.86,31.36 47.254,31.754 48,31.754 48.48,32.234 48.48,32.4 48.68,32.6 v6(48.8,32.6)
  L11 w0.1: v5(48.4,32.2) v6(48.8,32.6)
  L12 w0.09: v5(48.4,32.2) v6(48.8,32.6)
DRAM_DQS4_P: U1.AD18 U5.F3 | length 32
  L1 w0.09: U1.AD18@35.3,24 35.6,24 35.95,23.65 36.85,23.65 37.3,24.1 37.3,25.046 38.054,25.8 v1(38.5,25.8)
  L10 w0.085: v1(38.5,25.8) 38.5,26.104 37.837,26.767 37.837,26.999 37.536,27.3 36.5,27.3 36.186,27.614 36.186,28.146 36.5,28.46 37.46,28.46 37.8,28.8 37.8,29.396 38.96,30.556 38.96,31.076 39.274,31.39 39.806,31.39 40.12,31.076 40.12,29.776 40.27,29.626 40.57,29.626 40.72,29.776 40.72,31.7 41.034,32.014 41.566,32.014 41.88,31.7 41.88,30.616 42.03,30.466 42.33,30.466 42.48,30.616 42.48,31.38 42.932,31.832 45.463,31.832 45.98,31.316 45.98,30.816 46.13,30.666 46.43,30.666 46.58,30.816 46.58,31.476 47.138,32.034 47.884,32.034 48.2,32.35 48.2,32.5 48.1,32.6 v6(48,32.6)
  L11 w0.1: v5(47.6,32.2) v6(48,32.6)
  L12 w0.09: v5(47.6,32.2) v6(48,32.6)
DRAM_DQS5_N: U1.AE20 U5.B7 | length 18.5
  L1 w0.09: U1.AE20@36.1,25.6 36.19,25.51 36.356,25.51 37.4,26.554 37.4,26.946 37.654,27.2 37.892,27.2 38.322,26.77 38.678,26.77 38.908,27 39.1,27 v1(39.2,26.9)
  L10 w0.085: v1(39.2,26.9) 38.963,27.137 38.963,27.392 38.78,27.574 38.78,28.4 39.248,28.868 39.552,28.868 39.8,28.62 39.8,27.5 40.28,27.02 41.416,27.02 41.896,27.5 41.896,28.396 44.1,30.6 44.6,30.6 45.32,29.88 45.32,29.647 45.073,29.4 v6(44.8,29.4)
  L11 w0.1: v6(44.8,29.4) v5(45.2,29.8)
  L12 w0.09: v6(44.8,29.4) v5(45.2,29.8)
DRAM_DQS5_P: U1.AD20 U5.C7 | length 18.5
  L1 w0.09: U1.AD20@35.3,25.6 35.612,25.6 35.957,25.945 36.438,25.945 37.15,26.657 37.15,27.05 37.55,27.45 37.995,27.45 38.245,27.2 v1(38.5,27.2)
  L10 w0.085: v1(38.5,27.2) 38.5,28.516 39.132,29.148 39.668,29.148 40.08,28.736 40.08,27.616 40.396,27.3 41.3,27.3 41.616,27.616 41.616,28.512 43.984,30.88 44.716,30.88 45.6,29.996 v6(45.6,29.4)
  L11 w0.1: v6(45.6,29.4) v5(46,29.8)
  L12 w0.09: v6(45.6,29.4) v5(46,29.8)
DRAM_DQS6_N: U1.AE23 U4.B7 | length 17.2
  L1 w0.09: U1.AE23@36.1,28 36.1,28.141 36.164,28.205 37.212,28.205 37.6,28.593 37.6,30.1 37.8,30.3 37.8,31.1 38.06,31.36 38.36,31.36 38.459,31.26 38.741,31.26 39.081,31.6 v2(39.2,31.6) ; v2(44.4,33) v3(44.8,32.6)
  L2 w0.1: v3(38.9,31.9) v2(39.2,31.6) ; v2(44.4,33) v3(44.8,32.6)
  L3 w0.085: v3(38.9,31.9) 39.22,31.58 40.08,31.58 40.6,32.1 43.916,32.1 44.316,31.7 44.696,31.7 45.266,31.13 45.585,31.13 45.755,31.3 45.755,31.619 45.3,32.074 45.3,32.373 45.073,32.6 v3(44.8,32.6)
DRAM_DQS6_P: U1.AD23 U4.C7 | length 17.2
  L1 w0.09: U1.AD23@35.3,28 35.605,28 36.06,28.455 37.109,28.455 37.35,28.696 37.35,30.204 37.55,30.404 37.55,31.204 37.956,31.61 38.59,31.61 v2(38.6,31.6) ; v2(45.2,33) v3(45.6,32.6)
  L2 w0.1: v2(38.6,31.6) v3(38.9,31.3) ; v2(45.2,33) v3(45.6,32.6)
  L3 w0.085: v3(38.9,31.3) 40.196,31.3 40.716,31.82 43.8,31.82 43.91,31.71 44.2,31.42 44.58,31.42 45.15,30.85 45.701,30.85 46.035,31.184 46.035,31.735 45.58,32.19 45.58,32.58 v3(45.6,32.6)
DRAM_DQS7_N: U1.AA24 U4.G3 | length 25
  L1 w0.09: U1.AA24@32.9,28.8 32.9,29.112 33.3,29.512 33.3,30.401 34.099,31.2 36.303,31.2 36.552,30.952 36.552,30.752 v2(36.5,30.7) ; v2(48.4,29) v3(48.8,29.4)
  L2 w0.1: v2(36.5,30.7) v3(36.8,31) ; v2(48.4,29) v3(48.8,29.4)
  L3 w0.085: v3(36.8,31) 38.2,31 38.6,30.6 44.53,30.6 44.95,30.18 47.43,30.18 47.6,30.35 47.6,31.716 47.964,32.08 49.216,32.08 49.58,31.716 49.58,30.48 49.12,30.02 48.82,30.02 48.72,29.92 48.72,29.48 v3(48.8,29.4)
DRAM_DQS7_P: U1.AA25 U4.F3 | length 25
  L1 w0.09: U1.AA25@32.9,29.6 33.05,29.75 33.05,30.505 33.995,31.45 36.407,31.45 37.1,30.757 v2(37.1,30.7) ; v2(47.6,29) v3(48,29.4)
  L2 w0.1: v3(36.8,30.4) v2(37.1,30.7) ; v2(47.6,29) v3(48,29.4)
  L3 w0.085: v3(36.8,30.4) 36.8,30.469 37.051,30.72 38.084,30.72 38.484,30.32 44.414,30.32 44.824,29.91 ; 44.834,29.9 47.546,29.9 47.88,30.234 47.88,31.6 48.08,31.8 49.1,31.8 49.3,31.6 49.3,30.596 49.004,30.3 48.704,30.3 48.44,30.036 48.44,29.618 48.222,29.4 v3(48,29.4)
DRAM_RAS_B: U1.AB15 U2.J3 U3.J3 U4.J3 U5.J3 | length 70.1
  L1 w0.093: U1.AB15@33.7,21.6 v2(34.1,22) ; U2.J3@50.4,7.4 51.2,8.2 v1(51.2,9.3) ; U4.J3@50.4,29.4 51.2,30.2 v1(51.2,31.3)
  L2 w0.1: v3(33.8,21.7) v2(34.1,22)
  L3 w0.08: v3(33.8,21.7) 33.715,21.615 33.312,21.615 32.497,20.8 29.8,20.8 29.675,20.925 29.675,21.355 29.455,21.575 28.275,21.575 28.125,21.425 28.125,21.175 28.3,21 28.3,20.55 28.15,20.4 28.15,20.15 28.275,20.025 32.7,20.025 32.875,20.2 32.875,20.372 33.285,20.782 33.285,20.788 33.712,21.215 34.001,21.215 34.136,21.35 39.335,21.35 41.435,19.25 46.35,19.25 v4(46.5,19.1)
  L10 w0.08: v1(51.2,9.3) 51.2,9.6 52.533,10.933 52.533,12 52.255,12.278 52.255,13.345 50.975,14.625 50.762,14.625 50.425,14.962 50.425,15.305 50.13,15.6 49.825,15.6 49.175,16.25 47.05,16.25 46.8,16.5 46.8,17 46.95,17.15 47.65,17.15 47.8,17.3 47.8,17.55 47.65,17.7 46.95,17.7 46.8,17.85 46.8,18.533 46.5,18.833 v4(46.5,19.1) 46.5,19.2 47,19.7 47,22.4 47.55,22.95 48.68,22.95 49.955,24.225 50.238,24.225 50.575,24.562 50.575,25.109 52.533,27.068 52.533,29.074 51.2,30.407 v1(51.2,31.3)
  L12 w0.093: U3.J3@50.4,10.6 50.316,10.516 50.316,10.366 50.433,10.25 50.667,10.25 50.846,10.071 50.846,9.837 50.966,9.716 51.284,9.716 51.4,9.6 51.4,9.425 51.275,9.3 v1(51.2,9.3) ; U5.J3@50.4,32.6 50.316,32.516 50.316,32.366 50.433,32.25 50.667,32.25 50.846,32.071 50.846,31.837 50.966,31.716 51.284,31.716 51.4,31.6 51.4,31.425 51.275,31.3 v1(51.2,31.3)
DRAM_RESET_B: R7.2 U1.Y6 U2.T2 U3.T2 U4.T2 U5.T2 | length 80.6
  L1 w0.093: v1(31.7,14) U1.Y6@32.1,14.4 ; U2.T2@56,6.6 58.3,6.6 60,8.3 v1(60,9.3) ; U4.T2@56,28.6 58.3,28.6 60,30.3 v1(60,31.3)
  L3 w0.08: v1(31.7,14) 31.7,14.53 32.395,15.225 35.125,15.225 35.3,15.4 37.37,15.4 37.545,15.575 55.558,15.575 57.1,17.117 57.1,17.7 57.6,18.2 58.3,18.2 58.9,18.8 59.2,18.8 v4(60.8,20.4)
  L10 w0.08: v1(60,9.3) 61.1,10.4 61.1,18.231 60.8,18.531 v4(60.8,20.4) 60.8,23.425 61.35,23.975 61.35,29.95 v1(60,31.3)
  L12 w0.093: v1@31.8,14.1 v1(31.7,14) 32.5,14 32.6,14.1 R7.2@33,14.1 ; U3.T2@56,11.4 59.3,11.4 60,10.7 v1(60,9.3) ; U5.T2@56,33.4 59.3,33.4 60,32.7 v1(60,31.3)
DRAM_SDBA0: U1.AC15 U2.M2 U3.M2 U4.M2 U5.M2 | length 80.2
  L1 w0.093: U1.AC15@34.5,21.6 v2(34.9,22) ; U2.M2@52.775,6.625 52.95,6.625 53.075,6.75 53.075,6.925 52.925,7.075 52.665,7.075 52.4,7.34 52.4,7.6 52.725,7.925 52.959,7.925 53.2,8.166 v1(53.2,8.7) ; U4.M2@52.775,28.625 52.95,28.625 53.075,28.75 53.075,28.925 52.925,29.075 52.665,29.075 52.4,29.34 52.4,29.6 52.725,29.925 52.959,29.925 53.2,30.166 v1(53.2,30.7)
  L2 w0.1: v3(34.6,21.7) v2(34.9,22)
  L3 w0.08: v3(34.6,21.7) 34.7,21.6 39.418,21.6 41.518,19.5 46.7,19.5 46.9,19.3 47.575,19.3 48.15,18.725 50.75,18.725 50.9,18.875 50.9,19.217 50.642,19.475 49.454,19.475 v4(49.279,19.3)
  L10 w0.08: v1(53.2,8.7) 53.2,9.634 55.175,11.609 55.175,12.78 54.955,13 54.43,13 54.107,13.323 54.107,13.593 54.336,13.821 54.336,14.091 54.127,14.3 53.857,14.3 53.579,14.021 53.309,14.021 53.1,14.23 53.1,14.5 53.575,14.975 53.575,15.355 53.355,15.575 53.025,15.575 52.65,15.2 52.38,15.2 52.171,15.409 52.171,15.658 51.35,16.479 51.35,17.9 51.2,18.05 50.95,18.05 50.8,17.9 50.8,17.4 50.65,17.25 50.4,17.25 50.25,17.4 50.25,17.9 50.1,18.05 49.85,18.05 49.7,17.9 49.7,17.65 49.55,17.5 49.3,17.5 49.15,17.65 49.15,18.4 49.3,18.55 50.9,18.55 51.05,18.7 51.05,18.95 50.9,19.1 49.479,19.1 v4(49.279,19.3) 49.279,20.179 49.429,20.329 49.679,20.329 49.829,20.179 49.829,19.771 49.979,19.621 50.229,19.621 50.379,19.771 50.379,20.179 50.529,20.329 50.759,20.329 51.9,21.47 51.9,22.6 52.05,22.75 52.667,22.75 52.817,22.9 52.817,23.15 52.667,23.3 52,23.3 51.85,23.45 51.85,23.7 52,23.85 53.15,23.85 53.3,24 53.3,24.25 53.15,24.4 52.55,24.4 52.4,24.55 52.4,25 52.6,25.2 54.25,25.2 54.4,25.35 54.4,25.6 54.25,25.75 53.65,25.75 53.5,25.9 53.5,26.15 53.65,26.3 55.03,26.3 55.975,27.245 55.975,27.744 53.2,30.519 v1(53.2,30.7)
  L12 w0.093: U3.M2@52.8,11.4 52.4,11 52.4,10.4 53.2,9.6 53.2,9.321 v1(53.2,8.7) ; U5.M2@52.8,33.4 52.4,33 52.4,32.4 53.2,31.6 v1(53.2,30.7)
DRAM_SDBA1: U1.Y15 U2.N8 U3.N8 U4.N8 U5.N8 | length 77.1
  L1 w0.093: U1.Y15@32.1,21.6 v2(32.5,21.2) ; U2.N8@53.6,11.4 53.325,11.4 53.225,11.3 53.225,11.025 53.325,10.925 53.775,10.925 53.925,10.775 53.925,10.575 54.625,9.875 56.55,9.875 56.8,9.625 v1(56.8,9.3) ; U4.N8@53.6,33.4 53.325,33.4 53.225,33.3 53.225,33.025 53.325,32.925 53.775,32.925 53.925,32.775 53.925,32.575 54.625,31.875 56.55,31.875 56.8,31.625 v1(56.8,31.3)
  L2 w0.1: v3(32.2,21.5) v2(32.5,21.2)
  L3 w0.08: v3(32.2,21.5) 32.125,21.575 32.125,22.155 32.555,22.585 32.815,22.585 33.725,23.495 33.725,23.755 33.995,24.025 36.775,24.025 36.9,23.9 48.9,23.9 49.6,23.2 49.6,21.17 50.045,20.725 51.025,20.725 51.5,21.2 54.7,21.2 v4(54.9,21)
  L10 w0.08: v1(56.8,9.3) 56.8,9.946 58.45,11.596 58.45,17.371 56.6,19.221 56.6,19.33 54.93,21 v4(54.9,21) 54.725,21.175 54.725,21.425 54.9,21.6 55.078,21.6 55.317,21.361 55.573,21.361 55.675,21.463 55.675,21.725 55.381,22.019 55.381,22.211 58.8,25.63 58.8,28.554 56.8,30.554 v1(56.8,31.3)
  L12 w0.093: U3.N8@53.6,6.6 53.925,6.925 53.925,7.825 54.225,8.125 56.355,8.125 56.8,8.57 v1(56.8,9.3) ; U5.N8@53.6,28.6 53.925,28.925 53.925,29.825 54.225,30.125 56.355,30.125 56.8,30.57 v1(56.8,31.3)
DRAM_SDBA2: U1.AB12 U2.M3 U3.M3 U4.M3 U5.M3 | length 72.4
  L1 w0.093: v2(33.3,19.6) U1.AB12@33.7,19.2 ; U2.M3@52.8,7.4 52.8,7.483 53.6,8.283 v1(53.6,9.3) ; U4.M3@52.8,29.4 52.8,29.483 53.6,30.283 v1(53.6,31.3)
  L2 w0.1: v2(33.3,19.6) v3(33.6,19.3)
  L3 w0.08: v3(33.6,19.3) 33.203,19.3 32.9,18.997 32.9,17.8 33.125,17.575 33.455,17.575 33.675,17.355 33.675,17.025 33.9,16.8 35.9,16.8 36.1,17 36.1,18 36.325,18.225 36.738,18.225 37.113,18.6 37.5,18.6 37.633,18.733 37.633,18.918 37.8,19.085 38.118,19.085 38.285,18.918 38.285,18.515 38.5,18.3 39.365,18.3 40.665,17 44.487,17 44.762,17.275 45.521,17.275 46.046,16.75 52.15,16.75 52.5,17.1 v4(52.5,17.5)
  L10 w0.08: v1(53.6,9.3) 53.6,9.67 55.975,12.045 55.975,12.755 55.53,13.2 54.9,13.2 54.6,13.5 54.6,14.7 54.475,14.825 54.145,14.825 53.925,15.045 53.925,15.355 54.145,15.575 54.575,15.575 54.7,15.7 54.7,16.4 54.55,16.55 54.3,16.55 54.15,16.4 54.15,16.15 53.8,15.8 52.35,15.8 52.2,15.95 52.2,16.2 52.35,16.35 53.5,16.35 53.65,16.5 53.65,16.75 53.5,16.9 51.9,16.9 51.75,17.05 51.75,17.3 51.9,17.45 52.45,17.45 v4(52.5,17.5) 52.6,17.6 52.6,18 51,19.6 51,20.2 52.1,21.3 52.1,21.85 53.1,22.85 53.1,23.07 54.675,24.645 54.675,25.145 56.775,27.245 56.775,27.555 56.13,28.2 55.873,28.2 53.6,30.473 v1(53.6,31.3)
  L12 w0.093: U3.M3@52.8,10.6 52.8,10.333 52.883,10.25 53.167,10.25 53.246,10.171 53.246,9.837 53.366,9.716 53.684,9.716 53.8,9.6 53.8,9.425 53.675,9.3 v1(53.6,9.3) ; U5.M3@52.8,32.6 52.8,32.333 52.883,32.25 53.167,32.25 53.246,32.171 53.246,31.837 53.366,31.716 53.684,31.716 53.8,31.6 53.8,31.425 53.675,31.3 v1(53.6,31.3)
DRAM_SDCKE0: R6.2 U1.Y11 U2.K9 U3.K9 U4.K9 U5.K9 | length 81.5
  L1 w0.093: U1.Y11@32.1,18.4 32.2,18.4 32.6,18.8 33.1,18.8 33.3,18.6 33.3,18.2 33.5,18 37.7,18 R6.2@38.2,17.5 v2(38.8,17.5) ; v1(50.4,9.3) 50.4,9.7 50.9,10.2 51.3,10.2 51.525,10.425 51.525,10.9 51.4,11.025 50.975,11.025 50.8,11.2 50.8,11.5 50.6,11.7 50.6,11.9 50.9,12.2 U2.K9@51.2,12.2 ; v1(50.4,31.3) 50.4,31.7 50.9,32.2 51.3,32.2 51.525,32.425 51.525,32.9 51.4,33.025 50.975,33.025 50.8,33.2 50.8,33.5 50.6,33.7 50.6,33.9 50.9,34.2 U4.K9@51.2,34.2
  L2 w0.1: v3(38.5,17.8) v2(38.8,17.5)
  L3 w0.08: v3(38.5,17.8) 36.97,17.8 36.725,17.555 36.725,16.725 36.95,16.5 37.2,16.5 37.35,16.65 37.35,17.08 37.5,17.23 37.75,17.23 37.9,17.08 37.9,16.65 38.05,16.5 38.3,16.5 38.45,16.65 38.45,17.08 38.6,17.23 38.85,17.23 39,17.08 39,16.65 39.15,16.5 39.4,16.5 39.55,16.65 39.55,16.98 39.7,17.13 39.95,17.13 40.1,16.98 40.1,16.65 40.25,16.5 44.8,16.5 45,16.7 v4(45.1,16.7)
  L10 w0.08: v1(50.4,9.3) 50.4,9.6 51.948,11.148 51.948,11.974 51.685,12.237 51.685,13.198 50.658,14.225 50.596,14.225 50.221,14.6 49.787,14.6 49.3,15.087 49.3,15.325 48.825,15.8 48.187,15.8 47.937,15.55 47.15,15.55 46.4,16.3 45.75,16.3 45.6,16.45 45.6,16.7 45.75,16.85 46.2,16.85 46.35,17 46.35,17.25 46.2,17.4 45.65,17.4 45.5,17.55 45.5,17.8 45.65,17.95 46.2,17.95 46.35,18.1 46.35,18.35 45.7,19 45.3,19 45,18.7 45,17.375 45.3,17.075 45.3,16.9 v4(45.1,16.7) 44.802,16.7 44.25,17.253 44.25,18.65 45.2,19.6 45.2,22.1 46.55,23.45 48.5,23.45 49.625,24.575 49.625,24.955 49.987,25.317 50.1,25.317 52,27.217 52,28.9 50.4,30.5 v1(50.4,31.3)
  L12 w0.093: v1(50.4,9.3) 50.4,8.487 50.888,8 51.075,8 51.525,7.55 51.525,7.225 51.3,7 51.1,7 50.8,6.7 50.8,6.2 U3.K9@51.2,5.8 ; v1(50.4,31.3) 50.4,30.487 50.888,30 51.075,30 51.525,29.55 51.525,29.225 51.3,29 51.1,29 50.8,28.7 50.8,28.2 U5.K9@51.2,27.8
DRAM_SDODT0: U1.AC16 U2.K1 U3.K1 U4.K1 U5.K1 | length 79.1
  L1 w0.093: v2(34.1,22.8) U1.AC16@34.5,22.4 ; v1(50,8.7) 50,7.34 50.265,7.075 50.6,7.075 50.725,6.95 50.725,5.7 50.825,5.6 51,5.6 U2.K1@51.2,5.8 ; v1(50,30.7) 50,29.34 50.265,29.075 50.6,29.075 50.725,28.95 50.725,27.7 50.825,27.6 51,27.6 U4.K1@51.2,27.8
  L2 w0.1: v2(34.1,22.8) v3(34.4,23.1)
  L3 w0.08: v3(34.4,23.1) 34.93,23.1 35.48,23.65 48.833,23.65 49.35,23.133 49.35,21.05 48.925,20.625 47.509,20.625 47.3,20.834 47.3,21.2 47.15,21.35 45,21.35 44.85,21.5 v4(44.7,21.5)
  L10 w0.08: v1(50,8.7) 50.025,8.725 50.025,9.574 51.4,10.949 51.4,11.416 51.198,11.618 51.198,11.928 51.4,12.13 51.4,13.138 50.138,14.4 49.704,14.4 49.004,15.1 49.004,15.296 48.725,15.575 48.245,15.575 48,15.33 47,15.33 46.28,16.05 45.12,16.05 43.9,17.27 43.9,18.7 44.9,19.7 44.9,21.3 v4(44.7,21.5) 44.45,21.5 44.25,21.3 44.25,20.4 44.1,20.25 43.8,20.25 43.65,20.4 43.65,22.55 43.8,22.7 44.05,22.7 44.2,22.55 44.2,22.3 44.35,22.15 44.6,22.15 44.75,22.3 44.75,22.55 44.9,22.7 45.4,22.7 46.4,23.7 48.417,23.7 49.425,24.708 49.425,25.038 51.5,27.113 51.5,27.7 51.225,27.975 51.225,28.4 51.5,28.675 51.5,29 50,30.5 v1(50,30.7)
  L12 w0.093: v1(50,8.7) 50,10.66 50.365,11.025 50.485,11.025 50.725,11.265 50.725,11.725 U3.K1@51.2,12.2 ; v1(50,30.7) 50,32.66 50.365,33.025 50.485,33.025 50.725,33.265 50.725,33.725 U5.K1@51.2,34.2
DRAM_WE_B: U1.AB16 U2.L3 U3.L3 U4.L3 U5.L3 | length 70.9
  L1 w0.093: v2(32.5,22.8) 33.3,22.8 U1.AB16@33.7,22.4 ; U2.L3@52,7.4 52,7.483 52.8,8.283 v1(52.8,9.3) ; U4.L3@52,29.4 52,29.483 52.8,30.283 v1(52.8,31.3)
  L2 w0.1: v3(32.2,23.1) v2(32.5,22.8)
  L3 w0.08: v3(32.2,23.1) 32.2,23.325 32.125,23.4 32.125,24.555 32.395,24.825 32.655,24.825 32.925,25.095 32.925,25.355 33.145,25.575 34.255,25.575 34.805,25.025 36.738,25.025 37.338,24.425 51.175,24.425 51.65,23.95 51.65,23.05 51.5,22.9 51.25,22.9 51.1,22.75 51.1,22.45 51.25,22.3 51.5,22.3 51.65,22.15 51.65,21.85 51.5,21.7 51.2,21.7 50.7,21.2 v4(50.7,21.1)
  L10 w0.08: v1(52.8,9.3) 52.8,9.6 54.575,11.375 54.575,12.1 54.375,12.3 54.375,12.755 54.05,13.08 53.895,13.08 51.875,15.1 51.875,15.421 50.046,17.25 49.2,17.25 48.9,17.55 48.9,20.4 49.125,20.625 50.325,20.625 50.7,21 v4(50.7,21.1) 51.05,21.45 51.525,21.45 51.675,21.6 51.675,21.85 51.525,22 50.9,22 50.75,22.15 50.75,22.4 50.9,22.55 51.525,22.55 51.675,22.7 51.675,22.95 51.525,23.1 50.925,23.1 50.775,23.25 50.775,23.5 50.925,23.65 51.5,23.65 52.125,24.275 52.125,25.179 53.771,26.825 54.925,26.825 55.2,27.1 55.2,28.166 52.8,30.566 v1(52.8,31.3)
  L12 w0.093: U3.L3@52,10.6 51.916,10.516 51.916,10.366 52.033,10.25 52.267,10.25 52.446,10.071 52.446,9.837 52.566,9.716 52.8,9.716 53,9.516 53,9.425 52.875,9.3 v1(52.8,9.3) ; U5.L3@52,32.6 51.925,32.525 51.925,32.325 52,32.25 52.267,32.25 52.375,32.142 52.375,31.758 52.433,31.7 52.817,31.7 52.921,31.596 52.921,31.396 52.825,31.3 v1(52.8,31.3)
EN_1V375: Q5.3 R93.2 R132.1 U11.27 | length 24.7
  L10 w0.08: v6(4.15,22.95) 3.2,22 3.2,18.475 2.725,18 2.725,16.745 3.1,16.37 v6(3.1,15.5) 3.1,12.7 3.8,12 3.8,11.2 4.162,10.838 4.162,8.696 4.759,8.1 4.759,7.541 4.9,7.4 5.9,6.4 6.3,6.4 v6(6.5,6.2)
  L11 w0.1: v6(3.1,15.5) v5(3.1,15.9) ; v6(4.15,22.95) v5(4.55,22.95) ; v6(6.5,6.2) v5(6.9,6.2)
  L12 w0.093: v5(3.1,15.9) 3.65,15.35 Q5.3@3.65,14.6 4.35,13.9 R132.1@4.8,13.9 ; U11.27@4.55,22.4 v5(4.55,22.95) ; v5(6.9,6.2) R93.2@7.5,5.6
ENET_LED_LINK: J1.56 R81.2 | length 7.9
  L1 w0.093: R81.2@24.2,38.5 v2(24.2,39.1)
  L2 w0.1: v3(24.2,38.7) v2(24.2,39.1)
  L3 w0.08: v4(20.5,38.6) 21.425,38.6 21.6,38.775 24.125,38.775 v3(24.2,38.7)
  L10 w0.08: v4(20.5,38.6) 20.5,39 20.883,39.383 v6(21.35,39.383)
  L11 w0.1: v6(21.35,39.383) v5(21.75,39.383)
  L12 w0.093: J1.56@21.75,38.07 v5(21.75,39.383)
ENET_LED_RX: J1.55 R82.2 | length 12
  L1 w0.093: v2(22.5,37.9) R82.2@22.5,38.5
  L2 w0.1: v2(22.5,37.9) v3(22.8,38.2)
  L3 w0.08: v4(22.4,38.2) v3(22.8,38.2)
  L10 w0.08: v6(21.35,31.017) 20.312,32.055 20.312,34.012 20.7,34.4 21.4,34.4 21.777,34.777 21.777,36.8 22.4,37.423 v4(22.4,38.2)
  L11 w0.1: v6(21.35,31.017) v5(21.75,31.017)
  L12 w0.093: v5(21.75,31.017) J1.55@21.75,32.33
ENET_REF_CLK: R36.2 U1.V22 | length 23
  L1 w0.093: R36.2@12.4,26.7 12.5,26.7 v2(13,26.2) ; U1.V22@30.5,27.2 v2(30.9,26.8)
  L2 w0.1: v3(12.7,26.5) v2(13,26.2) ; v3(30.6,27.1) v2(30.9,26.8)
  L3 w0.08: v3(12.7,26.5) 13,26.8 13.897,26.8 14.282,26.415 14.518,26.415 14.618,26.515 16.465,26.515 16.6,26.65 17.65,26.65 17.65,26.647 18.672,25.625 19.055,25.625 19.275,25.845 19.275,26.105 19.545,26.375 19.855,26.375 20.155,26.075 21.325,26.075 21.6,25.8 23.103,25.8 23.485,26.182 23.485,26.885 24.2,27.6 26.1,27.6 26.2,27.5 27.7,27.5 27.85,27.35 28.95,27.35 29.125,27.175 30.525,27.175 v3(30.6,27.1)
ENET_REF_CLK_R: R36.1 R99.2 U8.41 | length 4.7
  L1 w0.093: U8.41@11.75,31.51 11.75,31.005 11.775,30.98 11.775,30.325 R99.2@12.4,29.7 13,29.1 13,28.1 12.6,27.7 R36.1@12.4,27.7
ETH_ISET: R84.1 U8.48 | length 1.9
  L1 w0.2: U8.48@15.25,31.51 16.3,31.51 16.39,31.6 R84.1@17,31.6 ; R84.1@16.89,31.51 R84.1@17,31.4
ETH_OSCI_25MHZ: C175.1 U8.46 Y3.2 | length 6.7
  L1 w0.093: U8.46@14.25,31.51 14.25,30.95 v1(14.4,30.8)
  L12 w0.093: Y3.2@13.9,27.85 13.85,27.8 12.4,27.8 12.05,28.15 12.05,28.85 12.8,29.6 13.3,29.6 C175.1@13.9,30.2 14.4,30.7 v1(14.4,30.8)
ETH_OSCO_25MHZ: C176.1 U8.45 Y3.1 | length 6.8
  L1 w0.093: v1@13.6,30.7 13.75,30.85 U8.45@13.75,31.51
  L12 w0.093: Y3.1@9.6,27.8 11.3,27.8 11.65,28.15 11.65,28.95 12.7,30 C176.1@12.7,30.2 13.1,30.2 13.3,30.4 13.3,30.55 13.55,30.8 v1(13.6,30.8)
